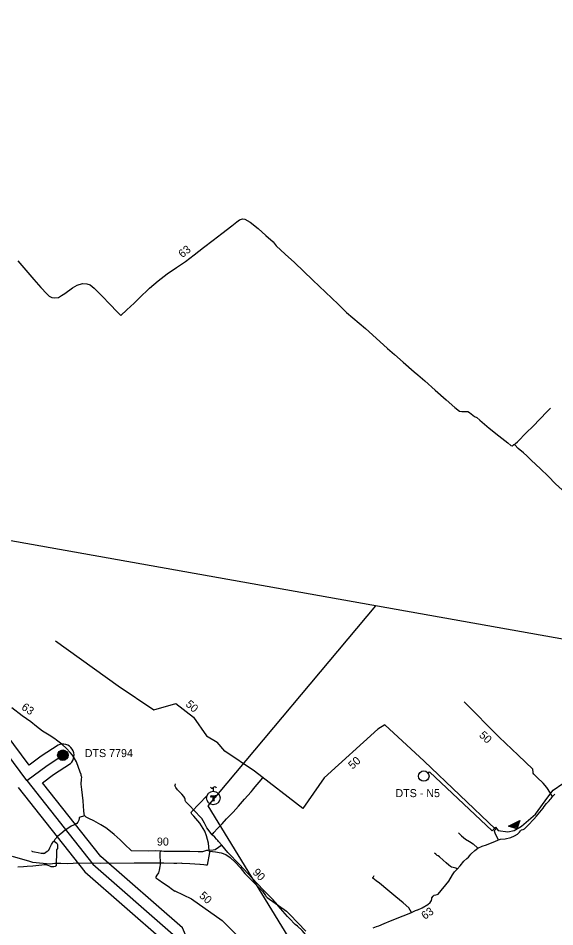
# Model space of a CAD drawing. Extents: x -444841 to -429545, y -1135312 to -1129851.
# Drawn here: x -441650 to -441113, y -1131902 to -1130994 of the extents above; entities that cross this region are included whole.
import ezdxf

# ---------------------------------------------------------------- set-up
doc = ezdxf.new("R2010")
doc.units = 0
for name, color, linetype in [('Vrstva 10', 7, 'Continuous'), ('Vrstva 11', 7, 'Continuous'), ('Vrstva 13', 7, 'Continuous'), ('Vrstva 15', 7, 'Continuous'), ('Vrstva 18', 7, 'Continuous'), ('Vrstva 19', 7, 'Continuous'), ('Vrstva 21', 7, 'Continuous'), ('Vrstva 27', 7, 'Continuous'), ('Vrstva 30', 7, 'Continuous'), ('Vrstva 35', 7, 'Continuous'), ('Vrstva 38', 7, 'Continuous'), ('Vrstva 57', 7, 'Continuous'), ('Vrstva 58', 7, 'Continuous'), ('Vrstva 59', 7, 'Continuous')]:
    doc.layers.add(name, color=color, linetype=linetype)

msp = doc.modelspace()

# ---------------------------------------------------------------- linework, layer by layer
at = {"layer": 'Vrstva 10'}
for points in [[(-441640.89, -1131756.15), (-441702.27, -1131673.76), (-441764.98, -1131592.78), (-441865.73, -1131598.93), (-441963.38, -1131605.66), (-442041.7, -1131537.14), (-442118.49, -1131453.57), (-442200.5, -1131363.12), (-442284.59, -1131268.2), (-442327.18, -1131223.28), (-442343.56, -1131201.55), (-442413.9, -1131123), (-442481.24, -1131047.9), (-442527.87, -1130994.29)], [(-441640.89, -1131756.15), (-441620.46, -1131740.89), (-441605.03, -1131730.87)], [(-441640.89, -1131756.15), (-441574.87, -1131839.72), (-441494.51, -1131910), (-441452.12, -1132008.18), (-441404.98, -1132108.37), (-441353.98, -1132209.5)]]:
    msp.add_lwpolyline(points, dxfattribs=at)
at = {"layer": 'Vrstva 11'}
for radius in [5.25, 4.55, 3.85, 3.15, 2.45, 1.75, 1.05, 0.35]:
    msp.add_circle((-441604.92, -1131730.72), radius, dxfattribs=at)
at = {"layer": 'Vrstva 15'}
for points in [[(-441638.65, -1131740.75), (-441693.51, -1131667.11), (-441759.84, -1131581.45), (-441866.44, -1131587.95), (-441959.57, -1131594.37), (-442034.01, -1131529.25), (-442110.37, -1131446.15), (-442192.31, -1131355.77), (-442276.35, -1131260.91), (-442335.34, -1131194.23), (-442405.71, -1131115.66), (-442473, -1131040.62), (-442511.53, -1130996.32)], [(-441609.7, -1131720.85), (-441626.75, -1131731.86), (-441638.65, -1131740.75)], [(-441625.25, -1131758.2), (-441614.16, -1131749.92), (-441597.4, -1131739.08)], [(-441649.52, -1131762.97), (-441582.87, -1131847.33), (-441503.62, -1131916.64), (-441462.15, -1132012.71), (-441414.87, -1132113.19), (-441362.91, -1132216.23)], [(-441347.71, -1132197.5), (-441395.09, -1132103.55), (-441442.09, -1132003.66), (-441485.39, -1131903.36), (-441566.87, -1131832.11), (-441625.25, -1131758.2)]]:
    msp.add_lwpolyline(points, dxfattribs=at)
msp.add_arc((-441604.8, -1131730.81), 11.1, 311.79584, 116.18861, dxfattribs=at)
at = {"layer": 'Vrstva 18'}
msp.add_lwpolyline([(-441240.01, -1131749.2), (-441238.26, -1131747.45), (-441175.66, -1131806.42), (-441172.3, -1131802.77), (-441169.53, -1131805.83), (-441159.91, -1131807.29), (-441153.5, -1131805.83), (-441146.21, -1131801.6), (-441132.22, -1131789.8), (-441119.9, -1131772.52), (-441114.72, -1131765.75), (-441105.1, -1131759.04)], dxfattribs=at)
for points in [[(-441159.46, -1131801.53), (-441148.12, -1131796.03), (-441151.04, -1131804.45)], [(-441157.63, -1131801.42), (-441149.34, -1131797.39), (-441151.47, -1131803.55)], [(-441155.81, -1131801.31), (-441150.55, -1131798.76), (-441151.9, -1131802.66)], [(-441153.98, -1131801.2), (-441151.77, -1131800.13), (-441152.34, -1131801.77)]]:
    msp.add_lwpolyline(points, close=True, dxfattribs=at)
at = {"layer": 'Vrstva 19'}
msp.add_circle((-441243.99, -1131751.59), 5.25, dxfattribs=at)
at = {"layer": 'Vrstva 27'}
for points in [[(-441649.8, -1131236.79), (-441641.93, -1131246.03), (-441634.02, -1131255.28), (-441626.84, -1131263.4), (-441620.8, -1131269.9), (-441618.52, -1131271.93), (-441615.92, -1131273.3), (-441613.07, -1131273.85), (-441609.41, -1131273.3), (-441606.19, -1131271.55), (-441603.01, -1131269.27), (-441595.42, -1131263.8), (-441590.59, -1131261.06), (-441585.27, -1131259.54), (-441580.88, -1131259.66), (-441577.58, -1131260.86), (-441573.76, -1131263.98), (-441565.49, -1131272.23), (-441557.79, -1131280.18), (-441550.6, -1131287.63), (-441546.96, -1131291.54), (-441540.82, -1131285.87), (-441533.76, -1131279.14), (-441528.74, -1131274.06), (-441518.37, -1131264.2), (-441509.62, -1131256.91), (-441500.72, -1131249.71), (-441491.22, -1131243.44), (-441482.37, -1131237.59), (-441473.59, -1131230.69), (-441464.18, -1131223.45), (-441454.7, -1131216.17), (-441445.83, -1131209.45), (-441436.11, -1131201.7), (-441431.06, -1131197.76), (-441428.13, -1131195.72), (-441425.25, -1131194.76), (-441422.89, -1131195.02), (-441417.74, -1131198.28), (-441409.55, -1131204.58), (-441401.92, -1131211.33), (-441394.76, -1131217.83), (-441391.47, -1131221.72), (-441382.74, -1131230.03), (-441373.35, -1131238.55), (-441354.83, -1131255.97), (-441329.57, -1131280.04), (-441321.21, -1131288.41), (-441302.32, -1131304.54), (-441291.66, -1131313.89)], [(-441291.66, -1131313.89), (-441280.17, -1131324.28), (-441273.35, -1131330.22), (-441264.79, -1131337.87), (-441253.66, -1131347.51), (-441250, -1131350.63)], [(-441250, -1131350.63), (-441243.07, -1131356.55), (-441232.5, -1131365.87), (-441221.53, -1131375.61), (-441212.85, -1131383.34), (-441208.45, -1131386.85), (-441205.9, -1131387.26), (-441199.98, -1131387.43), (-441198.18, -1131388.32), (-441193.4, -1131392.26), (-441191.1, -1131393.44), (-441187.98, -1131395.87), (-441178.69, -1131403.9), (-441168.92, -1131411.77), (-441160.09, -1131418.73), (-441156.93, -1131421.31), (-441155.76, -1131421.57), (-441154.72, -1131420.97), (-441153.88, -1131420.39), (-441153.4, -1131420.22)], [(-441153.4, -1131420.22), (-441152.29, -1131419.36), (-441150.33, -1131417.47), (-441141.24, -1131408.38), (-441135.09, -1131402.23), (-441127.75, -1131394.7), (-441120.91, -1131387.67), (-441117.17, -1131383.97)], [(-441070.07, -1131500), (-441072.1, -1131497.84), (-441079.4, -1131490.47), (-441085.86, -1131484.44), (-441096.58, -1131474.12), (-441105.52, -1131465.46), (-441112.2, -1131459.56), (-441119.53, -1131451.89), (-441127.19, -1131444.62), (-441136.54, -1131435.94), (-441141.11, -1131431.57), (-441144.33, -1131428.63), (-441149.5, -1131424.16), (-441152.91, -1131420.45), (-441153.4, -1131420.22)], [(-441583.23, -1131791.47), (-441583.25, -1131791.11), (-441583.72, -1131789.23), (-441584.09, -1131786.42), (-441584.17, -1131781.66), (-441584.46, -1131776.27), (-441585.87, -1131764.86), (-441586.59, -1131759.56), (-441586.38, -1131754.73), (-441586.04, -1131752.7), (-441586.27, -1131751.87), (-441586.6, -1131750.88), (-441586.64, -1131750.01), (-441587.64, -1131747.85), (-441591.3, -1131737.49), (-441593.57, -1131733.26), (-441595.37, -1131730.66), (-441597.76, -1131727.89), (-441601.3, -1131724.13), (-441606.04, -1131719.67), (-441611.19, -1131715.7), (-441613.01, -1131714.31), (-441618.73, -1131710.72), (-441625.34, -1131706.71), (-441631.41, -1131701.93), (-441636.97, -1131697.55), (-441645.5, -1131691.28), (-441655.91, -1131683.37)], [(-441115.18, -1131772.02), (-441116.69, -1131769.94), (-441117.44, -1131768.6), (-441121.03, -1131763.04), (-441124.79, -1131758.84), (-441130.49, -1131753.09), (-441133.82, -1131749.83), (-441134.69, -1131748.62), (-441134.75, -1131747.92), (-441134.53, -1131747.64)], [(-441455.56, -1131810.46), (-441460.98, -1131803.2), (-441463.4, -1131798.49), (-441466.12, -1131794.12), (-441467.11, -1131793.01), (-441473.16, -1131786.25), (-441478.16, -1131780.92), (-441482.04, -1131777.3), (-441482.5, -1131776.13), (-441482.71, -1131774.48), (-441482.98, -1131773.71), (-441483.92, -1131772.12), (-441485.98, -1131769.66), (-441490.35, -1131765.3), (-441491.97, -1131763.04), (-441492.36, -1131762.27), (-441493.02, -1131761.12)], [(-441455.56, -1131810.46), (-441453.88, -1131808.13), (-441450.26, -1131803.99), (-441445.7, -1131799.3), (-441441.13, -1131794.21), (-441434.66, -1131787.51), (-441429.43, -1131781.69), (-441423.3, -1131774.71), (-441416.59, -1131767.31), (-441414.98, -1131765.42), (-441414.17, -1131764.45)], [(-441210.73, -1131844.53), (-441207.65, -1131841.26), (-441203.87, -1131836.74), (-441200.83, -1131833.8), (-441199.24, -1131832.47), (-441198.06, -1131830.93), (-441197.08, -1131829.71), (-441196.62, -1131829.14), (-441193.1, -1131825.93), (-441189.87, -1131823.58), (-441185.67, -1131821.78), (-441181.45, -1131820.46), (-441178.95, -1131819.41), (-441172.98, -1131816.85), (-441169.19, -1131815.26), (-441167.18, -1131814.77), (-441162.77, -1131814.25), (-441157.01, -1131812.9), (-441153.19, -1131811.26), (-441150.34, -1131809.56), (-441148.35, -1131807.66), (-441147.46, -1131806.29), (-441146.24, -1131805.37), (-441144.8, -1131804.82), (-441143.31, -1131804.25), (-441142.52, -1131803.57), (-441138.35, -1131799.35), (-441135.18, -1131796), (-441134.07, -1131794.74), (-441131.4, -1131791.71), (-441128, -1131787.58), (-441124.74, -1131783.58), (-441123.56, -1131782.08), (-441121.3, -1131779.15), (-441118.8, -1131776.19), (-441117.57, -1131775.08), (-441116.76, -1131773.88), (-441115.18, -1131772.02), (-441113.91, -1131770.51), (-441112.95, -1131769.57)], [(-441583.23, -1131791.47), (-441588.59, -1131793.07), (-441588.62, -1131794.1), (-441589.02, -1131795.71), (-441589.91, -1131797.6), (-441590.91, -1131798.86), (-441592.54, -1131799.95), (-441596.45, -1131801.8), (-441599.08, -1131803.44), (-441602.55, -1131805.68), (-441607.05, -1131809.21), (-441609.83, -1131811.64), (-441612.79, -1131815.02), (-441613.39, -1131815.69), (-441613.67, -1131816.25)], [(-441507.6, -1131826.56), (-441511.94, -1131826.42), (-441519.51, -1131826.73), (-441536.18, -1131826.24), (-441537.75, -1131824.8), (-441541.88, -1131821.03), (-441547.77, -1131815.29), (-441553.73, -1131810.01), (-441557.34, -1131807.06), (-441561.98, -1131803.41), (-441566.91, -1131800.36), (-441573.9, -1131796.36), (-441578.97, -1131794.03), (-441581.46, -1131792.65), (-441582.86, -1131791.35), (-441583.23, -1131791.47)], [(-441450.05, -1131815.99), (-441451.21, -1131814.75), (-441453.11, -1131812.61), (-441455.56, -1131810.46)], [(-441209.2, -1131808.24), (-441208.53, -1131808.98), (-441206.35, -1131811.3), (-441202.34, -1131814.49), (-441198.43, -1131817.02), (-441194.73, -1131819.27), (-441189.87, -1131823.58)], [(-441169.17, -1131815.25), (-441172.27, -1131809.51), (-441173.48, -1131806.75), (-441173.32, -1131806.02), (-441172.32, -1131804.89), (-441171.74, -1131804.36)], [(-441613.67, -1131816.25), (-441613.53, -1131816.57), (-441612.13, -1131817.7), (-441610.97, -1131818.5), (-441610.5, -1131819.17), (-441610.27, -1131819.84), (-441610.27, -1131824.03), (-441611.27, -1131825.25), (-441611.21, -1131828.49), (-441611.51, -1131838.84), (-441611.51, -1131840.36), (-441611.58, -1131841.37), (-441612.12, -1131841.74), (-441612.76, -1131841.93), (-441613.89, -1131842.23), (-441614.83, -1131842.33), (-441615.3, -1131842.43), (-441615.6, -1131842.4), (-441616.57, -1131842.37), (-441617.83, -1131841.74), (-441619.57, -1131840.99), (-441621.61, -1131840.26), (-441623.48, -1131840.35), (-441626.03, -1131840.67), (-441635.05, -1131841.63), (-441640.49, -1131842.02), (-441644.14, -1131842.32), (-441650.08, -1131842.58)], [(-441623.98, -1131828.86), (-441623.23, -1131828.49), (-441620.59, -1131826.52), (-441619.44, -1131826.02), (-441619.04, -1131825.55), (-441617.9, -1131823.35), (-441616.27, -1131819.9), (-441614.59, -1131817.34), (-441613.78, -1131816.24), (-441613.67, -1131816.25)], [(-441446.05, -1131820.66), (-441452.67, -1131825.17), (-441454.75, -1131825.5), (-441459.83, -1131825.91), (-441460.47, -1131825.94), (-441461.17, -1131826.06), (-441465.14, -1131827.24), (-441469.54, -1131827.14), (-441477.88, -1131827.12), (-441483.15, -1131827.05), (-441490.67, -1131826.91), (-441495.14, -1131826.96), (-441500.84, -1131826.99), (-441504.02, -1131827), (-441506.11, -1131826.61), (-441507.6, -1131826.56)], [(-441449.23, -1131816.97), (-441450.05, -1131815.99)], [(-441446.05, -1131820.66), (-441449.23, -1131816.97)], [(-441358.13, -1131922.69), (-441358.79, -1131920.35), (-441359.9, -1131915.58), (-441360.88, -1131912.03), (-441361.98, -1131910.11), (-441365.48, -1131906.04), (-441370.4, -1131901.57), (-441372.5, -1131899.8), (-441378.42, -1131894.03), (-441380.23, -1131891.81), (-441389.51, -1131881.32), (-441391.67, -1131878.48), (-441392.57, -1131877.6), (-441393.49, -1131876.52), (-441394.31, -1131875.72), (-441396.91, -1131873.09), (-441404.5, -1131865.38), (-441415.65, -1131853.65), (-441428.33, -1131840.06), (-441439.82, -1131827.89), (-441446.05, -1131820.66)], [(-441623.98, -1131828.86), (-441625.11, -1131828.87), (-441626.72, -1131828.86), (-441629.49, -1131828.37), (-441633.19, -1131827.62), (-441634.99, -1131827.15), (-441635.57, -1131826.88), (-441635.8, -1131826.66), (-441635.7, -1131826.17)], [(-441507.6, -1131826.56), (-441507.81, -1131828.67), (-441507.63, -1131840.06), (-441508.08, -1131842.03), (-441508.73, -1131845.5), (-441509.42, -1131848.3), (-441510.85, -1131850.74), (-441511.82, -1131852.21), (-441512.07, -1131852.74), (-441511.79, -1131853.24), (-441510.96, -1131853.85), (-441508.92, -1131855.44), (-441505.16, -1131858), (-441500.67, -1131860.78), (-441498.15, -1131862.68), (-441496.56, -1131863.83), (-441493.05, -1131866.49)], [(-441210.73, -1131844.53), (-441210.88, -1131844.45), (-441212.01, -1131843.57), (-441214.53, -1131843.02), (-441216.19, -1131842.47), (-441217.15, -1131842), (-441218.87, -1131840.77), (-441221.67, -1131838.36), (-441224.68, -1131835.75), (-441228.2, -1131832.44), (-441229.61, -1131831.35), (-441230.52, -1131830.81), (-441232.07, -1131829.75), (-441233.39, -1131828.74)], [(-441250, -1131885.19), (-441245.6, -1131883.27), (-441240.07, -1131879.87), (-441237.67, -1131878.03), (-441236.15, -1131876.07), (-441236.02, -1131874.27), (-441235.86, -1131873.3), (-441234.73, -1131871.76), (-441233.68, -1131870.59), (-441232.1, -1131870.29), (-441230.75, -1131870.03), (-441229.65, -1131869.59), (-441226.6, -1131865.82), (-441221.92, -1131860.38), (-441219.05, -1131856.56), (-441215.19, -1131850.39), (-441213.15, -1131847.38), (-441210.73, -1131844.53)], [(-441279.99, -1131865.68), (-441288.24, -1131858.74), (-441291.55, -1131856.42), (-441295.03, -1131853.64), (-441295.07, -1131852.99), (-441294.42, -1131852.12), (-441293.49, -1131851.06)], [(-441256.36, -1131887.88), (-441257.5, -1131885.58), (-441259.13, -1131883.28), (-441264.76, -1131878.35), (-441271.96, -1131872.29), (-441279.99, -1131865.68)], [(-441294.74, -1131903.09), (-441291.2, -1131902.06), (-441289.07, -1131901.39), (-441283.58, -1131899.04), (-441277.2, -1131896.27), (-441264.78, -1131891.22), (-441258.49, -1131888.94), (-441256.36, -1131887.88)], [(-441256.36, -1131887.88), (-441252.41, -1131885.91), (-441250.2, -1131885.28), (-441250, -1131885.19)]]:
    msp.add_lwpolyline(points, dxfattribs=at)
at = {"layer": 'Vrstva 35'}
msp.add_line((-441414.17, -1131764.45), (-441405.01, -1131753.35), dxfattribs=at)
for points in [[(-441612.43, -1131616.42), (-441549.64, -1131661.27), (-441513.91, -1131685.5), (-441492.05, -1131679.09), (-441474.26, -1131692.79), (-441461.44, -1131711.45), (-441450.65, -1131717.86)], [(-441134.53, -1131747.64), (-441135.14, -1131744.84), (-441149.5, -1131730.63), (-441168.74, -1131712.86), (-441203.68, -1131677.48)], [(-441172.15, -1131804.57), (-441243.8, -1131736.77), (-441282.88, -1131700.35), (-441289.98, -1131704.79), (-441343.57, -1131753.35), (-441364.89, -1131784.14), (-441413.15, -1131746.84), (-441443.07, -1131726.61), (-441450.65, -1131717.86)], [(-441492.59, -1131759.5), (-441493.02, -1131761.12)], [(-441493.03, -1131866.42), (-441476.22, -1131874.15), (-441445.72, -1131895.91), (-441426.48, -1131915.01)]]:
    msp.add_lwpolyline(points, dxfattribs=at)
at = {"layer": 'Vrstva 57'}
for p, q in [((-441454.46, -1131762.99), (-441454.46, -1131766.74)), ((-441456.54, -1131772.31), (-441456.88, -1131771.97)), ((-441456.2, -1131771.94), (-441456.81, -1131771.33)), ((-441455.85, -1131771.58), (-441456.18, -1131771.25)), ((-441455.14, -1131771.58), (-441455.47, -1131771.25)), ((-441454.01, -1131772.01), (-441454.76, -1131771.25)), ((-441454.01, -1131772.72), (-441454.73, -1131771.99)), ((-441454.01, -1131773.43), (-441454.73, -1131772.7)), ((-441454.01, -1131774.13), (-441454.73, -1131773.41)), ((-441454.01, -1131774.84), (-441454.73, -1131774.11)), ((-441454.01, -1131775.55), (-441454.73, -1131774.82)), ((-441453.77, -1131776.49), (-441454.73, -1131775.53)), ((-441453.73, -1131771.58), (-441454.06, -1131771.25)), ((-441453.02, -1131771.58), (-441453.35, -1131771.25)), ((-441451.85, -1131772.04), (-441452.64, -1131771.25)), ((-441451.94, -1131771.25), (-441452.05, -1131771.14)), ((-441455.18, -1131776.49), (-441455.42, -1131776.26)), ((-441454.48, -1131776.49), (-441455.03, -1131775.94))]:
    msp.add_line(p, q, dxfattribs=at)
msp.add_lwpolyline([(-441457.37, -1131762.55), (-441456.85, -1131763.18), (-441456.2, -1131763.68), (-441455.81, -1131763.8), (-441455.4, -1131763.73), (-441454.88, -1131763.42), (-441454.46, -1131762.99), (-441454.04, -1131762.56), (-441453.52, -1131762.25), (-441453.12, -1131762.18), (-441452.72, -1131762.3), (-441452.07, -1131762.8), (-441451.56, -1131763.44)], dxfattribs=at)
msp.add_lwpolyline([(-441451.95, -1131771.14), (-441451.8, -1131772.53), (-441451.99, -1131772.53), (-441452.87, -1131771.58), (-441454.01, -1131771.58), (-441454.01, -1131775.7), (-441453.26, -1131776.31), (-441453.26, -1131776.49), (-441455.48, -1131776.49), (-441455.48, -1131776.31), (-441454.73, -1131775.7), (-441454.73, -1131771.58), (-441455.87, -1131771.58), (-441456.75, -1131772.53), (-441456.93, -1131772.53), (-441456.79, -1131771.14), (-441456.61, -1131771.14), (-441456.28, -1131771.25), (-441452.46, -1131771.25), (-441452.13, -1131771.14)], close=True, dxfattribs=at)
msp.add_circle((-441454.46, -1131773.49), 6.75, dxfattribs=at)
at = {"layer": 'Vrstva 58'}
for points in [[(-441458.63, -1131826.71), (-441458.75, -1131826.12), (-441459.43, -1131818.67), (-441461.19, -1131811.2), (-441463.08, -1131806.71), (-441467.94, -1131798.65), (-441474.04, -1131791.71), (-441474.91, -1131790.55), (-441475.86, -1131789.68), (-441476.57, -1131788.32), (-441476.35, -1131787.48), (-441460.9, -1131771.48)], [(-441458.63, -1131826.71), (-441458.45, -1131828.03), (-441460.51, -1131840.6), (-441462.12, -1131840.58), (-441464.01, -1131840.2), (-441467.67, -1131839.86), (-441467.92, -1131839.9), (-441478.07, -1131839.27), (-441485.5, -1131838.9), (-441486.57, -1131838.6), (-441491, -1131838.87), (-441493.98, -1131838.95), (-441503.91, -1131838.71), (-441505.64, -1131838.46), (-441505.98, -1131838.47), (-441530.08, -1131838.49), (-441531.52, -1131838.53), (-441533.72, -1131838.76), (-441567.68, -1131839.09), (-441591.58, -1131838.73), (-441594.77, -1131838.96), (-441600.69, -1131839.14), (-441606.95, -1131838.94), (-441612.91, -1131839.12), (-441617.7, -1131839.49), (-441617.97, -1131839.5), (-441634.83, -1131838.06), (-441635.82, -1131837.78), (-441638.02, -1131836.83), (-441655.24, -1131831.82)], [(-441458.63, -1131826.71), (-441458.13, -1131826.59), (-441452.15, -1131827.4), (-441446.66, -1131828.34), (-441442, -1131829.88), (-441437.74, -1131832.86), (-441432.15, -1131838.08), (-441427.71, -1131842.93), (-441422.92, -1131849), (-441417.2, -1131854.58), (-441405.44, -1131866.62), (-441402.28, -1131870.8), (-441401.85, -1131871.61), (-441400.63, -1131872.95), (-441381.21, -1131886.47), (-441377.89, -1131889.75), (-441362.06, -1131906.6)]]:
    msp.add_lwpolyline(points, dxfattribs=at)
at = {"layer": 'Vrstva 59'}
for points in [[(-440690.16, -1131688.83), (-443044.68, -1131269.31), (-443119.43, -1131255.99)], [(-441218.58, -1132174.63), (-441459.69, -1131781.27), (-441291.98, -1131581.6)]]:
    msp.add_lwpolyline(points, dxfattribs=at)

# ---------------------------------------------------------------- texts
at = {"layer": 'Vrstva 13'}
msp.add_text('DTS 7794', height=8, dxfattribs=at).set_placement((-441583.05, -1131732.63))
at = {"layer": 'Vrstva 21'}
msp.add_text('DTS - N5', height=8, dxfattribs=at).set_placement((-441272.41, -1131772.64))
at = {"layer": 'Vrstva 30'}
for s, rotation, p in [('63', 38.16299, (-441485.5, -1131234.18)), ('63', 325.53922, (-441647.03, -1131684.4)), ('90', 0.30155, (-441510.85, -1131821.07)), ('90', 313.54788, (-441415.77, -1131848.39)), ('63', 35.55505, (-441242.97, -1131895.41))]:
    msp.add_text(s, height=8, rotation=rotation, dxfattribs=at).set_placement(p)
at = {"layer": 'Vrstva 38'}
for rotation, p in [(318.19916, (-441482.79, -1131680.75)), (316.73294, (-441189.29, -1131711.52)), (42.17901, (-441315.25, -1131745.23)), (318.2295, (-441469.19, -1131872.05))]:
    msp.add_text('50', height=8, rotation=rotation, dxfattribs=at).set_placement(p)

doc.saveas('drawing.dxf')
